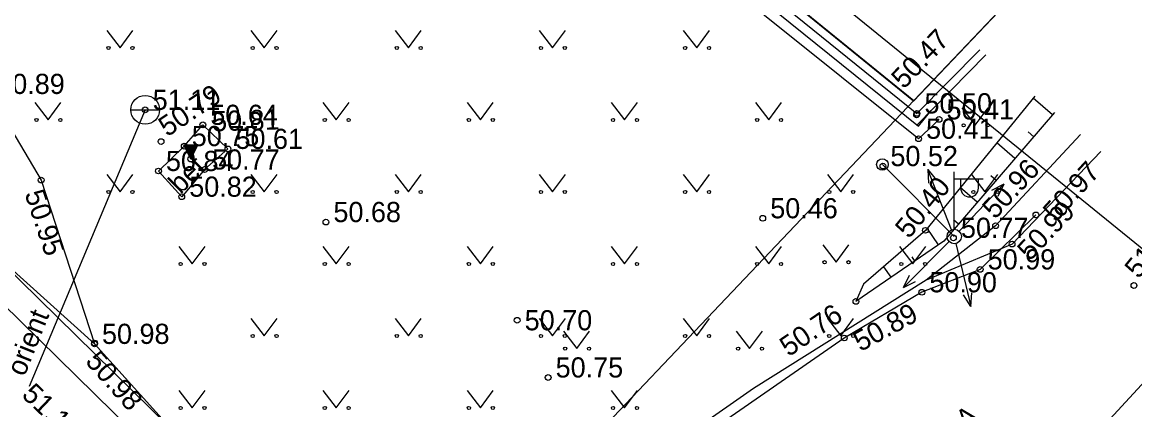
# Model space of a CAD drawing. Extents: x 640876 to 641418, y 6455595 to 6456085.
# Drawn here: x 641203.77 to 641242.36, y 6455760.88 to 6455774.33 of the extents above; entities that cross this region are included whole.
import ezdxf

# ---------------------------------------------------------------- set-up
doc = ezdxf.new("R2010")
doc.units = 0
for name, color, linetype in [('AED', 7, 'Continuous'), ('HALJASTUS', 7, 'Continuous'), ('KORGUS', 7, 'Continuous'), ('KTRASS', 7, 'Continuous'), ('MOOTKORG', 7, 'Continuous'), ('MOOTMPUNKT', 7, 'Continuous'), ('MOOTPIIR', 7, 'Continuous'), ('MPOHULIIN', 7, 'Continuous'), ('PIIR', 7, 'Continuous'), ('POST', 7, 'Continuous'), ('RAJATIS', 7, 'Continuous'), ('RAJATISEDET', 7, 'Continuous'), ('RELJEEF', 7, 'Continuous'), ('TEE', 7, 'Continuous'), ('VKAEV', 7, 'Continuous'), ('VTRASS', 7, 'Continuous')]:
    doc.layers.add(name, color=color, linetype=linetype)

msp = doc.modelspace()

# ---------------------------------------------------------------- linework, layer by layer
at = {"layer": 'AED'}
msp.add_lwpolyline([(641190.92, 6455807.146), (641198.401, 6455800.847), (641210.748, 6455790.622), (641234.804, 6455771.169), (641236.98, 6455773.379)], dxfattribs=at)
at = {"layer": 'HALJASTUS'}
for p, q in [((641206.699, 6455774.047), (641207.162, 6455773.44)), ((641207.162, 6455773.44), (641207.608, 6455774.047)), ((641211.699, 6455774.047), (641212.162, 6455773.44)), ((641212.162, 6455773.44), (641212.608, 6455774.047)), ((641216.699, 6455774.047), (641217.162, 6455773.44)), ((641217.162, 6455773.44), (641217.608, 6455774.047)), ((641221.699, 6455774.047), (641222.162, 6455773.44)), ((641222.162, 6455773.44), (641222.608, 6455774.047)), ((641226.699, 6455774.047), (641227.162, 6455773.44)), ((641227.162, 6455773.44), (641227.608, 6455774.047)), ((641204.199, 6455771.547), (641204.662, 6455770.94)), ((641204.662, 6455770.94), (641205.108, 6455771.547)), ((641214.199, 6455771.547), (641214.662, 6455770.94)), ((641214.662, 6455770.94), (641215.108, 6455771.547)), ((641219.199, 6455771.547), (641219.662, 6455770.94)), ((641219.662, 6455770.94), (641220.108, 6455771.547)), ((641224.199, 6455771.547), (641224.662, 6455770.94)), ((641224.662, 6455770.94), (641225.108, 6455771.547)), ((641229.199, 6455771.547), (641229.662, 6455770.94)), ((641229.662, 6455770.94), (641230.108, 6455771.547)), ((641236.361, 6455771.363), (641236.824, 6455770.756)), ((641236.824, 6455770.756), (641237.27, 6455771.363)), ((641206.699, 6455769.047), (641207.162, 6455768.44)), ((641207.162, 6455768.44), (641207.608, 6455769.047)), ((641211.699, 6455769.047), (641212.162, 6455768.44)), ((641212.162, 6455768.44), (641212.608, 6455769.047)), ((641216.699, 6455769.047), (641217.162, 6455768.44)), ((641217.162, 6455768.44), (641217.608, 6455769.047)), ((641221.699, 6455769.047), (641222.162, 6455768.44)), ((641222.162, 6455768.44), (641222.608, 6455769.047)), ((641226.699, 6455769.047), (641227.162, 6455768.44)), ((641227.162, 6455768.44), (641227.608, 6455769.047)), ((641231.699, 6455769.047), (641232.162, 6455768.44)), ((641232.162, 6455768.44), (641232.608, 6455769.047)), ((641236.699, 6455769.047), (641237.162, 6455768.44)), ((641237.162, 6455768.44), (641237.608, 6455769.047)), ((641209.199, 6455766.547), (641209.662, 6455765.94)), ((641209.662, 6455765.94), (641210.108, 6455766.547)), ((641214.199, 6455766.547), (641214.662, 6455765.94)), ((641214.662, 6455765.94), (641215.108, 6455766.547)), ((641219.199, 6455766.547), (641219.662, 6455765.94)), ((641219.662, 6455765.94), (641220.108, 6455766.547)), ((641224.199, 6455766.547), (641224.662, 6455765.94)), ((641224.662, 6455765.94), (641225.108, 6455766.547)), ((641229.199, 6455766.547), (641229.662, 6455765.94)), ((641229.662, 6455765.94), (641230.108, 6455766.547)), ((641231.537, 6455766.607), (641232, 6455766)), ((641232, 6455766), (641232.446, 6455766.607)), ((641234.199, 6455766.547), (641234.662, 6455765.94)), ((641234.662, 6455765.94), (641235.108, 6455766.547)), ((641211.699, 6455764.047), (641212.162, 6455763.44)), ((641212.162, 6455763.44), (641212.608, 6455764.047)), ((641216.699, 6455764.047), (641217.162, 6455763.44)), ((641217.162, 6455763.44), (641217.608, 6455764.047)), ((641221.699, 6455764.047), (641222.162, 6455763.44)), ((641222.162, 6455763.44), (641222.608, 6455764.047)), ((641226.699, 6455764.047), (641227.162, 6455763.44)), ((641227.162, 6455763.44), (641227.608, 6455764.047)), ((641231.699, 6455764.047), (641232.162, 6455763.44)), ((641232.162, 6455763.44), (641232.608, 6455764.047)), ((641222.537, 6455763.607), (641223, 6455763)), ((641223, 6455763), (641223.446, 6455763.607)), ((641228.537, 6455763.607), (641229, 6455763)), ((641229, 6455763), (641229.446, 6455763.607)), ((641209.199, 6455761.547), (641209.662, 6455760.94)), ((641209.662, 6455760.94), (641210.108, 6455761.547)), ((641214.199, 6455761.547), (641214.662, 6455760.94)), ((641214.662, 6455760.94), (641215.108, 6455761.547)), ((641219.199, 6455761.547), (641219.662, 6455760.94)), ((641219.662, 6455760.94), (641220.108, 6455761.547)), ((641224.199, 6455761.547), (641224.662, 6455760.94)), ((641224.662, 6455760.94), (641225.108, 6455761.547))]:
    msp.add_line(p, q, dxfattribs=at)
for points in [[(641235.569, 6455770.96), (641234.859, 6455770.287), (641224.113, 6455778.911), (641210.288, 6455790.09), (641210.748, 6455790.622)], [(641210.518, 6455790.356), (641234.853, 6455770.722)], [(641210.518, 6455790.356), (641234.853, 6455770.722), (641235.297, 6455771.272)], [(641237.19, 6455773.202), (641234.79, 6455770.744)]]:
    msp.add_lwpolyline(points, dxfattribs=at)
for centre in [(641206.761, 6455773.44), (641207.59, 6455773.44), (641211.761, 6455773.44), (641212.59, 6455773.44), (641216.761, 6455773.44), (641217.59, 6455773.44), (641221.761, 6455773.44), (641222.59, 6455773.44), (641226.761, 6455773.44), (641227.59, 6455773.44), (641204.261, 6455770.94), (641205.09, 6455770.94), (641214.261, 6455770.94), (641215.09, 6455770.94), (641219.261, 6455770.94), (641220.09, 6455770.94), (641224.261, 6455770.94), (641225.09, 6455770.94), (641229.261, 6455770.94), (641230.09, 6455770.94), (641236.423, 6455770.756), (641237.252, 6455770.756), (641206.761, 6455768.44), (641207.59, 6455768.44), (641211.761, 6455768.44), (641212.59, 6455768.44), (641216.761, 6455768.44), (641217.59, 6455768.44), (641221.761, 6455768.44), (641222.59, 6455768.44), (641226.761, 6455768.44), (641227.59, 6455768.44), (641231.761, 6455768.44), (641232.59, 6455768.44), (641236.761, 6455768.44), (641237.59, 6455768.44), (641209.261, 6455765.94), (641210.09, 6455765.94), (641214.261, 6455765.94), (641215.09, 6455765.94), (641219.261, 6455765.94), (641220.09, 6455765.94), (641224.261, 6455765.94), (641225.09, 6455765.94), (641229.261, 6455765.94), (641230.09, 6455765.94), (641231.599, 6455766), (641232.428, 6455766), (641234.261, 6455765.94), (641235.09, 6455765.94), (641211.761, 6455763.44), (641212.59, 6455763.44), (641216.761, 6455763.44), (641217.59, 6455763.44), (641221.761, 6455763.44), (641222.59, 6455763.44), (641226.761, 6455763.44), (641227.59, 6455763.44), (641231.761, 6455763.44), (641232.59, 6455763.44), (641222.599, 6455763), (641223.428, 6455763), (641228.599, 6455763), (641229.428, 6455763), (641209.261, 6455760.94), (641210.09, 6455760.94), (641214.261, 6455760.94), (641215.09, 6455760.94), (641219.261, 6455760.94), (641220.09, 6455760.94), (641224.261, 6455760.94), (641225.09, 6455760.94)]:
    msp.add_circle(centre, 0.055, dxfattribs=at)
at = {"layer": 'KORGUS'}
for centre in [(641234.792, 6455771.115), (641208.583, 6455770.19), (641204.424, 6455768.853), (641214.302, 6455767.394), (641229.454, 6455767.526), (641238.93, 6455767.644), (641235.097, 6455767.108), (641237.531, 6455767.267), (641238.101, 6455766.631), (641242.331, 6455765.194), (641232.685, 6455764.64), (641220.936, 6455763.986), (641206.277, 6455763.195), (641232.281, 6455763.369), (641222.01, 6455761.998)]:
    msp.add_circle(centre, 0.1, dxfattribs=at)
at = {"layer": 'KTRASS'}
msp.add_lwpolyline([(641230.602, 6455748.736), (641246.182, 6455765.632)], dxfattribs=at)
at = {"layer": 'MOOTMPUNKT'}
for centre in [(641208.033, 6455771.292), (641234.804, 6455771.169), (641235.569, 6455770.96), (641210.031, 6455770.77), (641234.859, 6455770.287), (641209.387, 6455770.032), (641210.904, 6455769.935), (641209.616, 6455769.584), (641233.622, 6455769.338), (641208.493, 6455769.168), (641210.093, 6455769.219), (641209.301, 6455768.275), (641236.069, 6455766.847), (641236.996, 6455765.75), (641234.974, 6455764.956), (641206.274, 6455763.164)]:
    msp.add_circle(centre, 0.1, dxfattribs=at)
at = {"layer": 'MOOTPIIR'}
msp.add_lwpolyline([(641060.916, 6455895.936), (641100.061, 6455950.482), (641099.586, 6455952.159), (641069.132, 6455984.035), (641066.132, 6455988.623), (641076.463, 6456005.049), (641230.642, 6456010.048), (641237.36, 6455995.24), (641237.24, 6455992.81), (641236.258, 6455990.888), (641229.041, 6455971.315), (641203.026, 6455909.57), (641225.257, 6455906.847), (641239.512, 6455898.491), (641200.195, 6455851.697), (641192.016, 6455859.099), (641169.785, 6455829.138), (641192.025, 6455807.568), (641252.96, 6455758.075), (641231.388, 6455736.74), (641191.474, 6455775.975), (641152.419, 6455787.914), (641136.351, 6455788.307), (641049.066, 6455856.043)], dxfattribs=at)
at = {"layer": 'MPOHULIIN'}
for p, q in [((641235.182, 6455769.221), (641235.207, 6455768.746)), ((641235.182, 6455769.221), (641235.485, 6455768.855)), ((641236.005, 6455767.127), (641235.182, 6455769.221)), ((641236.268, 6455767.076), (641237.814, 6455768.711)), ((641237.814, 6455768.711), (641237.394, 6455768.486)), ((641237.814, 6455768.711), (641237.611, 6455768.28)), ((641235.92, 6455766.717), (641234.331, 6455765.123)), ((641236.096, 6455766.894), (641236.096, 6455766.894)), ((641236.096, 6455766.894), (641236.096, 6455766.894)), ((641236.096, 6455766.894), (641236.096, 6455766.894)), ((641236.096, 6455766.894), (641236.096, 6455766.894)), ((641236.153, 6455766.651), (641236.67, 6455764.461)), ((641234.331, 6455765.123), (641234.545, 6455765.548)), ((641234.331, 6455765.123), (641234.756, 6455765.337)), ((641236.67, 6455764.461), (641236.421, 6455764.866)), ((641236.67, 6455764.461), (641236.712, 6455764.934))]:
    msp.add_line(p, q, dxfattribs=at)
at = {"layer": 'PIIR'}
for points in [[(641216.67, 6455752.61), (641192, 6455776.86), (641152.58, 6455788.91), (641136.9, 6455789.33), (641119.28, 6455802.72), (641101.72, 6455816.27), (641098.61, 6455818.83), (641124.03, 6455849.78), (641139.51, 6455868.99), (641157, 6455885.69), (641191.84, 6455860.59), (641168.46, 6455829.03), (641191.37, 6455806.79), (641234.69, 6455771.62)], [(641234.68, 6455771.59), (641191.36, 6455806.82), (641199.12, 6455815.36), (641207.91, 6455825.07), (641250.06, 6455787.79)], [(641216.67, 6455752.61), (641182.28, 6455716.38), (641177.47, 6455716.39), (641127.83, 6455755.09), (641138.89, 6455768.28), (641129.48, 6455779.82), (641136.9, 6455789.33), (641152.58, 6455788.91), (641192, 6455776.86)]]:
    msp.add_lwpolyline(points, close=True, dxfattribs=at)
msp.add_lwpolyline([(641274.59, 6455777.38), (641265.59, 6455768.59), (641244.26, 6455745.67), (641222.48, 6455722.23), (641201.2, 6455700.54), (641180.13, 6455678.32), (641171.14, 6455668.19), (641142.12, 6455638.98), (641132.03, 6455627.4), (641101.1, 6455594.76), (641087.79, 6455611.35), (641100.72, 6455625.11), (641099.2, 6455626.54), (641113.86, 6455642.06), (641121.21, 6455649.84), (641140.58, 6455669.91), (641170.91, 6455704.35), (641182.28, 6455716.38), (641216.67, 6455752.61), (641234.69, 6455771.62), (641250.06, 6455787.79)], dxfattribs=at)
at = {"layer": 'POST'}
for p, q in [((641236.096, 6455767.144), (641236.096, 6455769.144)), ((641236.096, 6455768.894), (641237.096, 6455768.894)), ((641236.323, 6455768.573), (641236.323, 6455768.894)), ((641236.935, 6455768.573), (641236.935, 6455768.894)), ((641236.096, 6455766.894), (641236.096, 6455766.894))]:
    msp.add_line(p, q, dxfattribs=at)
msp.add_lwpolyline([(641233.605, 6455769.394), (641236.096, 6455766.894)], dxfattribs=at)
for centre, radius in [((641233.605, 6455769.394), 0.2), ((641236.096, 6455766.894), 0.25)]:
    msp.add_circle(centre, radius, dxfattribs=at)
msp.add_arc((641236.629, 6455768.573), 0.306, 180, 0, dxfattribs=at)
at = {"layer": 'RAJATIS'}
msp.add_lwpolyline([(641208.493, 6455769.168), (641209.387, 6455770.032), (641210.031, 6455770.77), (641210.904, 6455769.935), (641210.093, 6455769.219), (641209.301, 6455768.275)], close=True, dxfattribs=at)
at = {"layer": 'RAJATISEDET'}
for p, q in [((641209.616, 6455769.584), (641209.37, 6455770.071)), ((641209.862, 6455770.071), (641209.37, 6455770.071)), ((641209.378, 6455770.054), (641209.722, 6455769.793)), ((641209.397, 6455770.071), (641209.733, 6455769.815)), ((641209.404, 6455770.003), (641209.71, 6455769.77)), ((641209.43, 6455769.952), (641209.699, 6455769.747)), ((641209.439, 6455770.071), (641209.745, 6455769.838)), ((641209.456, 6455769.901), (641209.687, 6455769.725)), ((641209.48, 6455770.071), (641209.756, 6455769.861)), ((641209.481, 6455769.85), (641209.676, 6455769.702)), ((641209.507, 6455769.799), (641209.664, 6455769.679)), ((641209.521, 6455770.071), (641209.768, 6455769.883)), ((641209.562, 6455770.071), (641209.779, 6455769.906)), ((641209.604, 6455770.071), (641209.79, 6455769.929)), ((641209.616, 6455769.584), (641209.862, 6455770.071)), ((641209.645, 6455770.071), (641209.802, 6455769.951)), ((641209.686, 6455770.071), (641209.813, 6455769.974)), ((641209.727, 6455770.071), (641209.825, 6455769.997)), ((641209.769, 6455770.071), (641209.836, 6455770.019)), ((641209.81, 6455770.071), (641209.848, 6455770.042)), ((641209.851, 6455770.071), (641209.859, 6455770.065)), ((641209.533, 6455769.747), (641209.653, 6455769.657)), ((641209.559, 6455769.696), (641209.641, 6455769.634)), ((641209.585, 6455769.645), (641209.63, 6455769.611)), ((641209.611, 6455769.594), (641209.618, 6455769.588))]:
    msp.add_line(p, q, dxfattribs=at)
at = {"layer": 'RELJEEF'}
for p, q in [((641239.506, 6455771.115), (641238.834, 6455771.693)), ((641238.853, 6455770.357), (641238.658, 6455770.525)), ((641238.201, 6455769.599), (641237.57, 6455770.143)), ((641237.548, 6455768.842), (641237.365, 6455768.999)), ((641236.896, 6455768.084), (641236.306, 6455768.592)), ((641236.243, 6455767.326), (641236.072, 6455767.473)), ((641235.554, 6455766.609), (641235.159, 6455767.184)), ((641234.73, 6455766.043), (641234.634, 6455766.183)), ((641233.905, 6455765.477), (641233.652, 6455765.846))]:
    msp.add_line(p, q, dxfattribs=at)
for points in [[(641238.894, 6455771.767), (641235.097, 6455767.108), (641232.951, 6455765.233), (641232.685, 6455764.64)], [(641239.575, 6455771.195), (641235.73, 6455766.73), (641232.685, 6455764.64)]]:
    msp.add_lwpolyline(points, dxfattribs=at)
at = {"layer": 'TEE'}
for points in [[(641180.696, 6455804.462), (641181.867, 6455799.392), (641184.213, 6455789.95), (641190.34, 6455783.007), (641197.609, 6455777.363), (641202.64, 6455771.843), (641204.424, 6455768.853), (641206.274, 6455763.164)], [(641210.623, 6455756.753), (641209.995, 6455759.033), (641206.274, 6455763.164), (641201.573, 6455767.409), (641194.555, 6455773.807), (641189.469, 6455777.839), (641187.027, 6455774.627)], [(641240.478, 6455770.434), (641237.531, 6455767.267), (641235.127, 6455765.375)], [(641241.177, 6455769.846), (641238.101, 6455766.631), (641235.127, 6455765.375), (641229.134, 6455761.617), (641223.014, 6455757.336)], [(641238.93, 6455767.644), (641236.996, 6455765.75), (641234.974, 6455764.956), (641232.281, 6455763.369), (641225.754, 6455758.837), (641220.766, 6455754.323), (641218.145, 6455751.263), (641216.502, 6455750.988), (641215.165, 6455751.027), (641214.689, 6455751.315)]]:
    msp.add_lwpolyline(points, dxfattribs=at)
at = {"layer": 'VKAEV'}
msp.add_line((641207.533, 6455771.292), (641208.533, 6455771.292), dxfattribs=at)
msp.add_circle((641208.033, 6455771.292), 0.5, dxfattribs=at)
at = {"layer": 'VTRASS'}
msp.add_line((641208.033, 6455771.292), (641204.004, 6455761.683), dxfattribs=at)

# ---------------------------------------------------------------- texts
at = {"layer": 'KORGUS'}
for s, rotation, p in [(' 50.47', 46.1345, (641234.17, 6455771.799)), (' 50.79', 33.8733, (641208.583, 6455770.19)), (' 50.96', 47.1681, (641237.336, 6455767.274)), (' 50.97', 47.7373, (641239.448, 6455767.173)), (' 50.40', 50.8223, (641234.364, 6455766.586)), (' 50.95', 288.4761, (641203.76, 6455768.631)), (' 50.99', 46.6111, (641238.544, 6455765.826)), (' 51.07', 51.1443, (641242.331, 6455765.194)), (' 50.76', 34.4646, (641230.139, 6455762.55)), (' 50.89', 28.6328, (641232.616, 6455762.755)), (' 50.98', 311.6489, (641205.754, 6455762.73)), (' 51.14', 316.5071, (641203.525, 6455761.534))]:
    msp.add_text(s, height=0.7, rotation=rotation, dxfattribs=at).set_placement(p)
for s, p in [(' 50.46', (641229.454, 6455767.526)), (' 50.68', (641214.302, 6455767.394)), (' 50.70', (641220.936, 6455763.636)), (' 50.75', (641222.01, 6455761.998))]:
    msp.add_text(s, height=0.7, dxfattribs=at).set_placement(p)
at = {"layer": 'MOOTKORG'}
for s, p in [(' 50.89', (641202.64, 6455771.843)), (' 51.11', (641208.033, 6455771.292)), (' 50.50', (641234.804, 6455771.169)), (' 50.64', (641210.031, 6455770.77)), (' 50.41', (641235.569, 6455770.96)), (' 50.41', (641234.859, 6455770.287)), (' 50.75', (641209.387, 6455770.032)), (' 50.61', (641210.904, 6455769.935)), (' 50.84', (641208.493, 6455769.168)), (' 50.77', (641210.093, 6455769.219)), (' 50.52', (641233.622, 6455769.338)), (' 50.82', (641209.301, 6455768.275)), (' 50.77', (641236.069, 6455766.847)), (' 50.99', (641236.996, 6455765.75)), (' 50.90', (641234.974, 6455764.956)), (' 50.98', (641206.274, 6455763.164))]:
    msp.add_text(s, height=0.7, dxfattribs=at).set_placement(p)
at = {"layer": 'RAJATIS'}
msp.add_text('bet', height=0.7, rotation=44.6441, dxfattribs=at).set_placement((641209.26, 6455768.341))
at = {"layer": 'RAJATISEDET'}
msp.add_text(' 50.81', height=0.7, rotation=1.7147, dxfattribs=at).set_placement((641210.102, 6455770.536))
at = {"layer": 'TEE'}
msp.add_text('A', height=0.7, rotation=39.0355, dxfattribs=at).set_placement((641236.505, 6455760.148))
at = {"layer": 'VTRASS'}
msp.add_text('orient', height=0.7, rotation=68.1118, dxfattribs=at).set_placement((641203.843, 6455762.002))

doc.saveas('drawing.dxf')
